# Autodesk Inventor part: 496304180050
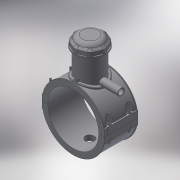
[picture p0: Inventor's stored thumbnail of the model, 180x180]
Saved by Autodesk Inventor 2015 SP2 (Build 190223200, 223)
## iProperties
Created: 2017-07
Part Number: 496304180050
Material: Generic
Description: PLASSON TAPPING SADDLE 180x50
Document SubType Name: Modeling
Designer: KIM
Mass: 1264.08 g
Surface Area: 2695.4 cm^2
Volume: 1264.08 cm^3
Density: 1 g/cm^3
Appearance: Default
Author: KIM
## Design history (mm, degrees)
derived "496304.ipt"
feature "Solid1::496304.ipt"
feature "Solid2::496304.ipt"
feature "Solid4::496304.ipt"
feature "Solid5::496304.ipt"
tag "TaggingFeature1"
body "Solid1"
body "Solid2"
other parameters: "B_" = 219, "L_" = 118, "d_t" = 6, "H_2" = 138, "H_1" = 24, "H_" = 174, "d1" = 205.2, "d148" = 2.7, "d160" = 2.7, "d169" = 3.375, "d192" = 6.3, "d2" = 219, "d3" = 45, "d4" = 118, "d5" = 0, "d6" = 0.1, "d8" = 0, "d19" = 6, "d20" = 6, "d21" = 70.8, "d23" = 0, "d24" = 35.4, "d26" = 0, "d29" = 3, "d31" = 6, "d32" = 0, "d33" = 0, "d34" = 0.6, "d40" = 106.704, "d41" = 72, "d43" = 0, "d45" = 0, "d47" = 173.4, "d70" = 15, "d72" = 0, "d73" = 6, "d75" = 5, "d76" = 0, "d77" = 9, "d79" = 15, "d80" = 47.2, "d82" = 5 deg, "d84" = 4, "d85" = 14, "d86" = 0, "d87" = 3, "d88" = 0, "d89" = 1, "d90" = 1, "d91" = 94.4, "d92" = 0, "d93" = 0.5, "d94" = 94.73684, "d96" = 209.304, "d97" = 2.36, "d98" = 0, "d102" = 1.8, "d120" = 140 deg, "d121" = 24.228, "d122" = 20 deg, "d123" = 410.4, "d124" = 123.12, "d126" = 0, "d143" = 185.4, "d145" = 19.38462, "d149" = 2.7, "d150" = 21.32308, "d153" = 118, "d154" = 0, "d156" = 102.6, "d157" = 160 deg, "d159" = 5.04, "d161" = 2.7, "d162" = 70.8, "d163" = 0, "d167" = 18, "d168" = 100.09756, "d170" = 3.375, "d172" = 0, "d173" = 1, "d176" = 20 deg, "d177" = 12.6, "d178" = 25.2, "d180" = 0, "d183" = 10.08, "d184" = 10.08, "d185" = 38.35, "d186" = 38.35, "d187" = 102.6, "d188" = 7.56, "d189" = 12.6, "d190" = 0, "d191" = 153.9, "d193" = 6.3, "d194" = 4.13, "d195" = 90 deg, "d197" = 0, "d199" = 0, "d200" = 12.6, "d202" = 0, "d203" = 138, "d204" = 68.4, "d205" = 50.4, "d206" = 61.2, "d207" = 103.5, "d208" = 107.64, "d209" = 128.34, "d210" = 61.92, "d211" = 72, "d212" = 57.6, "d213" = -0.9, "d216" = 0, "d217" = 18, "d218" = 18, "d219" = 3.6, "d224" = 0, "d230" = 3.6, "d233" = 6, "d236" = 109.5, "d237" = 35.4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
